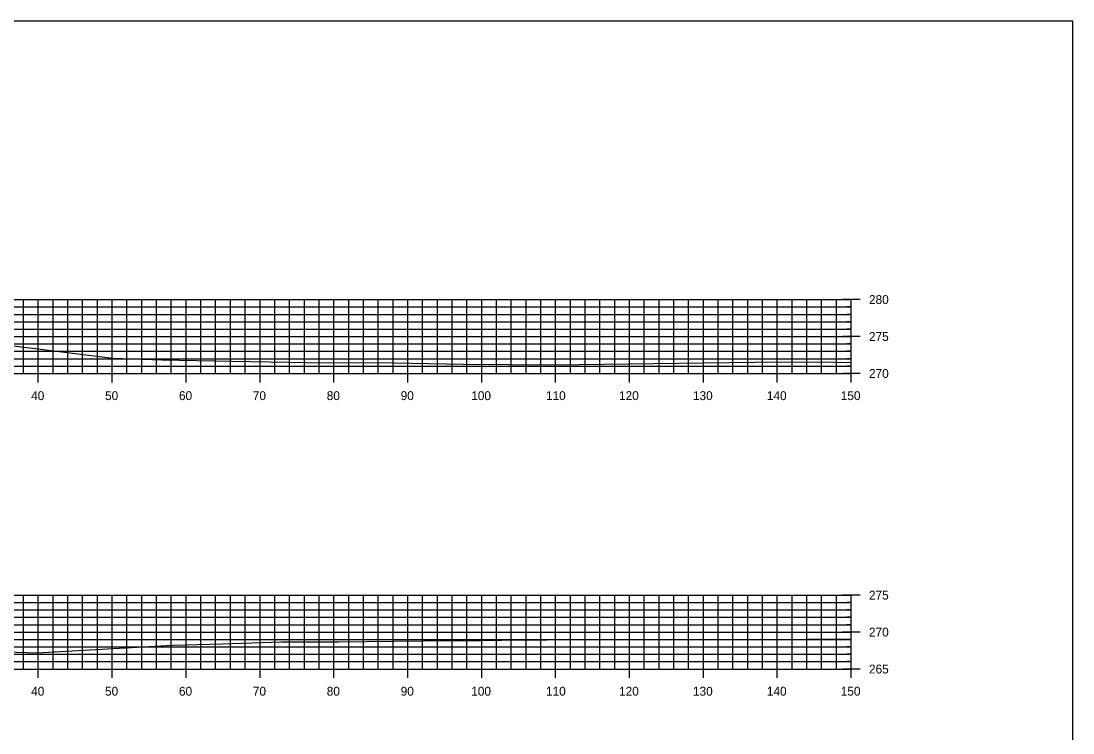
# Model space of a CAD drawing. Extents: x 1661012 to 1662122, y 670053 to 671852.
# Drawn here: x 1661629.7 to 1661772, y 671370.5 to 671466.8 of the extents above; entities that cross this region are included whole.
import ezdxf

# ---------------------------------------------------------------- set-up
doc = ezdxf.new("R2010")
doc.units = 0
for name, color, linetype in [('R_Concrete', 7, 'Continuous'), ('R_Concrete Hidden', 7, 'Continuous'), ('R_Erosion', 7, 'Continuous'), ('R_Exist Surface', 7, 'Continuous'), ('R_Proposed Road', 7, 'Continuous')]:
    doc.layers.add(name, color=color, linetype=linetype)

msp = doc.modelspace()

# ---------------------------------------------------------------- linework, layer by layer
at = {"layer": 'R_Concrete'}
for p, q in [((1661441.99, 671429.12), (1661741.99, 671429.12)), ((1661441.99, 671428.12), (1661741.99, 671428.12)), ((1661629.99, 671419.12), (1661629.99, 671429.12)), ((1661631.99, 671419.12), (1661631.99, 671429.12)), ((1661633.99, 671419.12), (1661633.99, 671429.12)), ((1661635.99, 671419.12), (1661635.99, 671429.12)), ((1661637.99, 671419.12), (1661637.99, 671429.12)), ((1661639.99, 671419.12), (1661639.99, 671429.12)), ((1661641.99, 671419.12), (1661641.99, 671429.12)), ((1661643.99, 671419.12), (1661643.99, 671429.12)), ((1661645.99, 671419.12), (1661645.99, 671429.12)), ((1661647.99, 671419.12), (1661647.99, 671429.12)), ((1661649.99, 671419.12), (1661649.99, 671429.12)), ((1661651.99, 671419.12), (1661651.99, 671429.12)), ((1661653.99, 671419.12), (1661653.99, 671429.12)), ((1661655.99, 671419.12), (1661655.99, 671429.12)), ((1661657.99, 671419.12), (1661657.99, 671429.12)), ((1661659.99, 671419.12), (1661659.99, 671429.12)), ((1661661.99, 671419.12), (1661661.99, 671429.12)), ((1661663.99, 671419.12), (1661663.99, 671429.12)), ((1661665.99, 671419.12), (1661665.99, 671429.12)), ((1661667.99, 671419.12), (1661667.99, 671429.12)), ((1661669.99, 671419.12), (1661669.99, 671429.12)), ((1661671.99, 671419.12), (1661671.99, 671429.12)), ((1661673.99, 671419.12), (1661673.99, 671429.12)), ((1661675.99, 671419.12), (1661675.99, 671429.12)), ((1661677.99, 671419.12), (1661677.99, 671429.12)), ((1661679.99, 671419.12), (1661679.99, 671429.12)), ((1661681.99, 671419.12), (1661681.99, 671429.12)), ((1661683.99, 671419.12), (1661683.99, 671429.12)), ((1661685.99, 671419.12), (1661685.99, 671429.12)), ((1661687.99, 671419.12), (1661687.99, 671429.12)), ((1661689.99, 671419.12), (1661689.99, 671429.12)), ((1661691.99, 671419.12), (1661691.99, 671429.12)), ((1661693.99, 671419.12), (1661693.99, 671429.12)), ((1661695.99, 671419.12), (1661695.99, 671429.12)), ((1661697.99, 671419.12), (1661697.99, 671429.12)), ((1661699.99, 671419.12), (1661699.99, 671429.12)), ((1661701.99, 671419.12), (1661701.99, 671429.12)), ((1661703.99, 671419.12), (1661703.99, 671429.12)), ((1661705.99, 671419.12), (1661705.99, 671429.12)), ((1661707.99, 671419.12), (1661707.99, 671429.12)), ((1661709.99, 671419.12), (1661709.99, 671429.12)), ((1661711.99, 671419.12), (1661711.99, 671429.12)), ((1661713.99, 671419.12), (1661713.99, 671429.12)), ((1661715.99, 671419.12), (1661715.99, 671429.12)), ((1661717.99, 671419.12), (1661717.99, 671429.12)), ((1661719.99, 671419.12), (1661719.99, 671429.12)), ((1661721.99, 671419.12), (1661721.99, 671429.12)), ((1661723.99, 671419.12), (1661723.99, 671429.12)), ((1661725.99, 671419.12), (1661725.99, 671429.12)), ((1661727.99, 671419.12), (1661727.99, 671429.12)), ((1661729.99, 671419.12), (1661729.99, 671429.12)), ((1661731.99, 671419.12), (1661731.99, 671429.12)), ((1661733.99, 671419.12), (1661733.99, 671429.12)), ((1661735.99, 671419.12), (1661735.99, 671429.12)), ((1661737.99, 671419.12), (1661737.99, 671429.12)), ((1661739.99, 671419.12), (1661739.99, 671429.12)), ((1661743.19, 671429.12), (1661740.79, 671429.12)), ((1661741.99, 671428.12), (1661741.39, 671428.12)), ((1661741.99, 671419.12), (1661741.99, 671429.12)), ((1661441.99, 671427.12), (1661741.99, 671427.12)), ((1661741.99, 671427.12), (1661741.39, 671427.12)), ((1661441.99, 671426.12), (1661741.99, 671426.12)), ((1661441.99, 671425.12), (1661741.99, 671425.12)), ((1661741.99, 671426.12), (1661741.39, 671426.12)), ((1661741.99, 671425.12), (1661741.39, 671425.12)), ((1661441.99, 671424.12), (1661741.99, 671424.12)), ((1661743.19, 671424.12), (1661740.79, 671424.12)), ((1661441.99, 671423.12), (1661741.99, 671423.12)), ((1661741.99, 671423.12), (1661741.39, 671423.12)), ((1661441.99, 671422.12), (1661741.99, 671422.12)), ((1661441.99, 671421.12), (1661741.99, 671421.12)), ((1661741.99, 671422.12), (1661741.39, 671422.12)), ((1661741.99, 671421.12), (1661741.39, 671421.12)), ((1661441.99, 671420.12), (1661741.99, 671420.12)), ((1661629.99, 671419.12), (1661629.99, 671419.72)), ((1661631.99, 671417.92), (1661631.99, 671420.32)), ((1661633.99, 671419.12), (1661633.99, 671419.72)), ((1661635.99, 671419.12), (1661635.99, 671419.72)), ((1661637.99, 671419.12), (1661637.99, 671419.72)), ((1661639.99, 671419.12), (1661639.99, 671419.72)), ((1661641.99, 671417.92), (1661641.99, 671420.32)), ((1661643.99, 671419.12), (1661643.99, 671419.72)), ((1661645.99, 671419.12), (1661645.99, 671419.72)), ((1661647.99, 671419.12), (1661647.99, 671419.72)), ((1661649.99, 671419.12), (1661649.99, 671419.72)), ((1661651.99, 671417.92), (1661651.99, 671420.32)), ((1661653.99, 671419.12), (1661653.99, 671419.72)), ((1661655.99, 671419.12), (1661655.99, 671419.72)), ((1661657.99, 671419.12), (1661657.99, 671419.72)), ((1661659.99, 671419.12), (1661659.99, 671419.72)), ((1661661.99, 671417.92), (1661661.99, 671420.32)), ((1661663.99, 671419.12), (1661663.99, 671419.72)), ((1661665.99, 671419.12), (1661665.99, 671419.72)), ((1661667.99, 671419.12), (1661667.99, 671419.72)), ((1661669.99, 671419.12), (1661669.99, 671419.72)), ((1661671.99, 671417.92), (1661671.99, 671420.32)), ((1661673.99, 671419.12), (1661673.99, 671419.72)), ((1661675.99, 671419.12), (1661675.99, 671419.72)), ((1661677.99, 671419.12), (1661677.99, 671419.72)), ((1661679.99, 671419.12), (1661679.99, 671419.72)), ((1661681.99, 671417.92), (1661681.99, 671420.32)), ((1661683.99, 671419.12), (1661683.99, 671419.72)), ((1661685.99, 671419.12), (1661685.99, 671419.72)), ((1661687.99, 671419.12), (1661687.99, 671419.72)), ((1661689.99, 671419.12), (1661689.99, 671419.72)), ((1661691.99, 671417.92), (1661691.99, 671420.32)), ((1661693.99, 671419.12), (1661693.99, 671419.72)), ((1661695.99, 671419.12), (1661695.99, 671419.72)), ((1661697.99, 671419.12), (1661697.99, 671419.72)), ((1661699.99, 671419.12), (1661699.99, 671419.72)), ((1661701.99, 671417.92), (1661701.99, 671420.32)), ((1661703.99, 671419.12), (1661703.99, 671419.72)), ((1661705.99, 671419.12), (1661705.99, 671419.72)), ((1661707.99, 671419.12), (1661707.99, 671419.72)), ((1661709.99, 671419.12), (1661709.99, 671419.72)), ((1661711.99, 671417.92), (1661711.99, 671420.32)), ((1661713.99, 671419.12), (1661713.99, 671419.72)), ((1661715.99, 671419.12), (1661715.99, 671419.72)), ((1661717.99, 671419.12), (1661717.99, 671419.72)), ((1661719.99, 671419.12), (1661719.99, 671419.72)), ((1661721.99, 671417.92), (1661721.99, 671420.32)), ((1661723.99, 671419.12), (1661723.99, 671419.72)), ((1661725.99, 671419.12), (1661725.99, 671419.72)), ((1661727.99, 671419.12), (1661727.99, 671419.72)), ((1661729.99, 671419.12), (1661729.99, 671419.72)), ((1661731.99, 671417.92), (1661731.99, 671420.32)), ((1661733.99, 671419.12), (1661733.99, 671419.72)), ((1661735.99, 671419.12), (1661735.99, 671419.72)), ((1661737.99, 671419.12), (1661737.99, 671419.72)), ((1661739.99, 671419.12), (1661739.99, 671419.72)), ((1661741.99, 671420.12), (1661741.39, 671420.12)), ((1661741.99, 671417.92), (1661741.99, 671420.32)), ((1661441.99, 671419.12), (1661741.99, 671419.12)), ((1661743.19, 671419.12), (1661740.79, 671419.12)), ((1661441.99, 671389.12), (1661741.99, 671389.12)), ((1661441.99, 671388.12), (1661741.99, 671388.12)), ((1661629.99, 671379.12), (1661629.99, 671389.12)), ((1661631.99, 671379.12), (1661631.99, 671389.12)), ((1661633.99, 671379.12), (1661633.99, 671389.12)), ((1661635.99, 671379.12), (1661635.99, 671389.12)), ((1661637.99, 671379.12), (1661637.99, 671389.12)), ((1661639.99, 671379.12), (1661639.99, 671389.12)), ((1661641.99, 671379.12), (1661641.99, 671389.12)), ((1661643.99, 671379.12), (1661643.99, 671389.12)), ((1661645.99, 671379.12), (1661645.99, 671389.12)), ((1661647.99, 671379.12), (1661647.99, 671389.12)), ((1661649.99, 671379.12), (1661649.99, 671389.12)), ((1661651.99, 671379.12), (1661651.99, 671389.12)), ((1661653.99, 671379.12), (1661653.99, 671389.12)), ((1661655.99, 671379.12), (1661655.99, 671389.12)), ((1661657.99, 671379.12), (1661657.99, 671389.12)), ((1661659.99, 671379.12), (1661659.99, 671389.12)), ((1661661.99, 671379.12), (1661661.99, 671389.12)), ((1661663.99, 671379.12), (1661663.99, 671389.12)), ((1661665.99, 671379.12), (1661665.99, 671389.12)), ((1661667.99, 671379.12), (1661667.99, 671389.12)), ((1661669.99, 671379.12), (1661669.99, 671389.12)), ((1661671.99, 671379.12), (1661671.99, 671389.12)), ((1661673.99, 671379.12), (1661673.99, 671389.12)), ((1661675.99, 671379.12), (1661675.99, 671389.12)), ((1661677.99, 671379.12), (1661677.99, 671389.12)), ((1661679.99, 671379.12), (1661679.99, 671389.12)), ((1661681.99, 671379.12), (1661681.99, 671389.12)), ((1661683.99, 671379.12), (1661683.99, 671389.12)), ((1661685.99, 671379.12), (1661685.99, 671389.12)), ((1661687.99, 671379.12), (1661687.99, 671389.12)), ((1661689.99, 671379.12), (1661689.99, 671389.12)), ((1661691.99, 671379.12), (1661691.99, 671389.12)), ((1661693.99, 671379.12), (1661693.99, 671389.12)), ((1661695.99, 671379.12), (1661695.99, 671389.12)), ((1661697.99, 671379.12), (1661697.99, 671389.12)), ((1661699.99, 671379.12), (1661699.99, 671389.12)), ((1661701.99, 671379.12), (1661701.99, 671389.12)), ((1661703.99, 671379.12), (1661703.99, 671389.12)), ((1661705.99, 671379.12), (1661705.99, 671389.12)), ((1661707.99, 671379.12), (1661707.99, 671389.12)), ((1661709.99, 671379.12), (1661709.99, 671389.12)), ((1661711.99, 671379.12), (1661711.99, 671389.12)), ((1661713.99, 671379.12), (1661713.99, 671389.12)), ((1661715.99, 671379.12), (1661715.99, 671389.12)), ((1661717.99, 671379.12), (1661717.99, 671389.12)), ((1661719.99, 671379.12), (1661719.99, 671389.12)), ((1661721.99, 671379.12), (1661721.99, 671389.12)), ((1661723.99, 671379.12), (1661723.99, 671389.12)), ((1661725.99, 671379.12), (1661725.99, 671389.12)), ((1661727.99, 671379.12), (1661727.99, 671389.12)), ((1661729.99, 671379.12), (1661729.99, 671389.12)), ((1661731.99, 671379.12), (1661731.99, 671389.12)), ((1661733.99, 671379.12), (1661733.99, 671389.12)), ((1661735.99, 671379.12), (1661735.99, 671389.12)), ((1661737.99, 671379.12), (1661737.99, 671389.12)), ((1661739.99, 671379.12), (1661739.99, 671389.12)), ((1661743.19, 671389.12), (1661740.79, 671389.12)), ((1661741.99, 671388.12), (1661741.39, 671388.12)), ((1661741.99, 671379.12), (1661741.99, 671389.12)), ((1661441.99, 671387.12), (1661741.99, 671387.12)), ((1661741.99, 671387.12), (1661741.39, 671387.12)), ((1661441.99, 671386.12), (1661741.99, 671386.12)), ((1661741.99, 671386.12), (1661741.39, 671386.12)), ((1661441.99, 671385.12), (1661741.99, 671385.12)), ((1661441.99, 671384.12), (1661741.99, 671384.12)), ((1661743.19, 671384.12), (1661740.79, 671384.12)), ((1661741.99, 671385.12), (1661741.39, 671385.12)), ((1661441.99, 671383.12), (1661741.99, 671383.12)), ((1661741.99, 671383.12), (1661741.39, 671383.12)), ((1661441.99, 671382.12), (1661741.99, 671382.12)), ((1661441.99, 671381.12), (1661741.99, 671381.12)), ((1661741.99, 671382.12), (1661741.39, 671382.12)), ((1661741.99, 671381.12), (1661741.39, 671381.12)), ((1661441.99, 671380.12), (1661741.99, 671380.12)), ((1661629.99, 671379.12), (1661629.99, 671379.72)), ((1661631.99, 671377.92), (1661631.99, 671380.32)), ((1661633.99, 671379.12), (1661633.99, 671379.72)), ((1661635.99, 671379.12), (1661635.99, 671379.72)), ((1661637.99, 671379.12), (1661637.99, 671379.72)), ((1661639.99, 671379.12), (1661639.99, 671379.72)), ((1661641.99, 671377.92), (1661641.99, 671380.32)), ((1661643.99, 671379.12), (1661643.99, 671379.72)), ((1661645.99, 671379.12), (1661645.99, 671379.72)), ((1661647.99, 671379.12), (1661647.99, 671379.72)), ((1661649.99, 671379.12), (1661649.99, 671379.72)), ((1661651.99, 671377.92), (1661651.99, 671380.32)), ((1661653.99, 671379.12), (1661653.99, 671379.72)), ((1661655.99, 671379.12), (1661655.99, 671379.72)), ((1661657.99, 671379.12), (1661657.99, 671379.72)), ((1661659.99, 671379.12), (1661659.99, 671379.72)), ((1661661.99, 671377.92), (1661661.99, 671380.32)), ((1661663.99, 671379.12), (1661663.99, 671379.72)), ((1661665.99, 671379.12), (1661665.99, 671379.72)), ((1661667.99, 671379.12), (1661667.99, 671379.72)), ((1661669.99, 671379.12), (1661669.99, 671379.72)), ((1661671.99, 671377.92), (1661671.99, 671380.32)), ((1661673.99, 671379.12), (1661673.99, 671379.72)), ((1661675.99, 671379.12), (1661675.99, 671379.72)), ((1661677.99, 671379.12), (1661677.99, 671379.72)), ((1661679.99, 671379.12), (1661679.99, 671379.72)), ((1661681.99, 671377.92), (1661681.99, 671380.32)), ((1661683.99, 671379.12), (1661683.99, 671379.72)), ((1661685.99, 671379.12), (1661685.99, 671379.72)), ((1661687.99, 671379.12), (1661687.99, 671379.72)), ((1661689.99, 671379.12), (1661689.99, 671379.72)), ((1661691.99, 671377.92), (1661691.99, 671380.32)), ((1661693.99, 671379.12), (1661693.99, 671379.72)), ((1661695.99, 671379.12), (1661695.99, 671379.72)), ((1661697.99, 671379.12), (1661697.99, 671379.72)), ((1661699.99, 671379.12), (1661699.99, 671379.72)), ((1661701.99, 671377.92), (1661701.99, 671380.32)), ((1661703.99, 671379.12), (1661703.99, 671379.72)), ((1661705.99, 671379.12), (1661705.99, 671379.72)), ((1661707.99, 671379.12), (1661707.99, 671379.72)), ((1661709.99, 671379.12), (1661709.99, 671379.72)), ((1661711.99, 671377.92), (1661711.99, 671380.32)), ((1661713.99, 671379.12), (1661713.99, 671379.72)), ((1661715.99, 671379.12), (1661715.99, 671379.72)), ((1661717.99, 671379.12), (1661717.99, 671379.72)), ((1661719.99, 671379.12), (1661719.99, 671379.72)), ((1661721.99, 671377.92), (1661721.99, 671380.32)), ((1661723.99, 671379.12), (1661723.99, 671379.72)), ((1661725.99, 671379.12), (1661725.99, 671379.72)), ((1661727.99, 671379.12), (1661727.99, 671379.72)), ((1661729.99, 671379.12), (1661729.99, 671379.72)), ((1661731.99, 671377.92), (1661731.99, 671380.32)), ((1661733.99, 671379.12), (1661733.99, 671379.72)), ((1661735.99, 671379.12), (1661735.99, 671379.72)), ((1661737.99, 671379.12), (1661737.99, 671379.72)), ((1661739.99, 671379.12), (1661739.99, 671379.72)), ((1661741.99, 671380.12), (1661741.39, 671380.12)), ((1661741.99, 671377.92), (1661741.99, 671380.32)), ((1661441.99, 671379.12), (1661741.99, 671379.12)), ((1661743.19, 671379.12), (1661740.79, 671379.12))]:
    msp.add_line(p, q, dxfattribs=at)
at = {"layer": 'R_Erosion'}
for points in [[(1661619.89, 671423.93), (1661642.07, 671421.19), (1661648.7, 671420.98), (1661658.22, 671420.81), (1661668.3, 671420.6), (1661680.15, 671420.55), (1661689.53, 671420.36), (1661701.83, 671420.31), (1661715.19, 671420.49), (1661728.97, 671420.67), (1661737.48, 671420.71), (1661741.99, 671420.62)], [(1661626.28, 671381.51), (1661631.76, 671381.33), (1661650.18, 671382.37), (1661656.89, 671382.52), (1661664.9, 671382.79), (1661672.61, 671382.82), (1661687.69, 671382.97), (1661689.57, 671382.96), (1661694.68, 671383.04), (1661707, 671383.13), (1661714.51, 671383.16), (1661729.96, 671383.14), (1661741.99, 671383.23)]]:
    msp.add_lwpolyline(points, dxfattribs=at)
at = {"layer": 'R_Exist Surface'}
for p, q in [((1661741.99, 671419.12), (1661741.99, 671429.12)), ((1661441.99, 671419.12), (1661741.99, 671419.12)), ((1661741.99, 671379.12), (1661741.99, 671389.12)), ((1661441.99, 671379.12), (1661741.99, 671379.12))]:
    msp.add_line(p, q, dxfattribs=at)
at = {"layer": 'R_Proposed Road'}
msp.add_lwpolyline([(1661411.99, 671274.12), (1661771.99, 671274.12), (1661771.99, 671466.82), (1661411.99, 671466.82)], close=True, dxfattribs=at)

# ---------------------------------------------------------------- texts
at = {"layer": 'R_Concrete Hidden'}
for s, p in [('280', (1661744.39, 671428.52)), ('275', (1661744.39, 671423.52)), ('270', (1661744.39, 671418.52)), ('40', (1661631.02, 671415.52)), ('50', (1661641.02, 671415.52)), ('60', (1661651.02, 671415.52)), ('70', (1661661.02, 671415.52)), ('80', (1661671.02, 671415.52)), ('90', (1661681.02, 671415.52)), ('100', (1661690.57, 671415.52)), ('110', (1661700.68, 671415.52)), ('120', (1661710.57, 671415.52)), ('130', (1661720.57, 671415.52)), ('140', (1661730.57, 671415.52)), ('150', (1661740.57, 671415.52)), ('275', (1661744.39, 671388.52)), ('270', (1661744.39, 671383.52)), ('265', (1661744.39, 671378.52)), ('40', (1661631.02, 671375.52)), ('50', (1661641.02, 671375.52)), ('60', (1661651.02, 671375.52)), ('70', (1661661.02, 671375.52)), ('80', (1661671.02, 671375.52)), ('90', (1661681.02, 671375.52)), ('100', (1661690.57, 671375.52)), ('110', (1661700.68, 671375.52)), ('120', (1661710.57, 671375.52)), ('130', (1661720.57, 671375.52)), ('140', (1661730.57, 671375.52)), ('150', (1661740.57, 671375.52))]:
    msp.add_text(s, height=1.2, dxfattribs=at).set_placement(p)

doc.saveas('drawing.dxf')
